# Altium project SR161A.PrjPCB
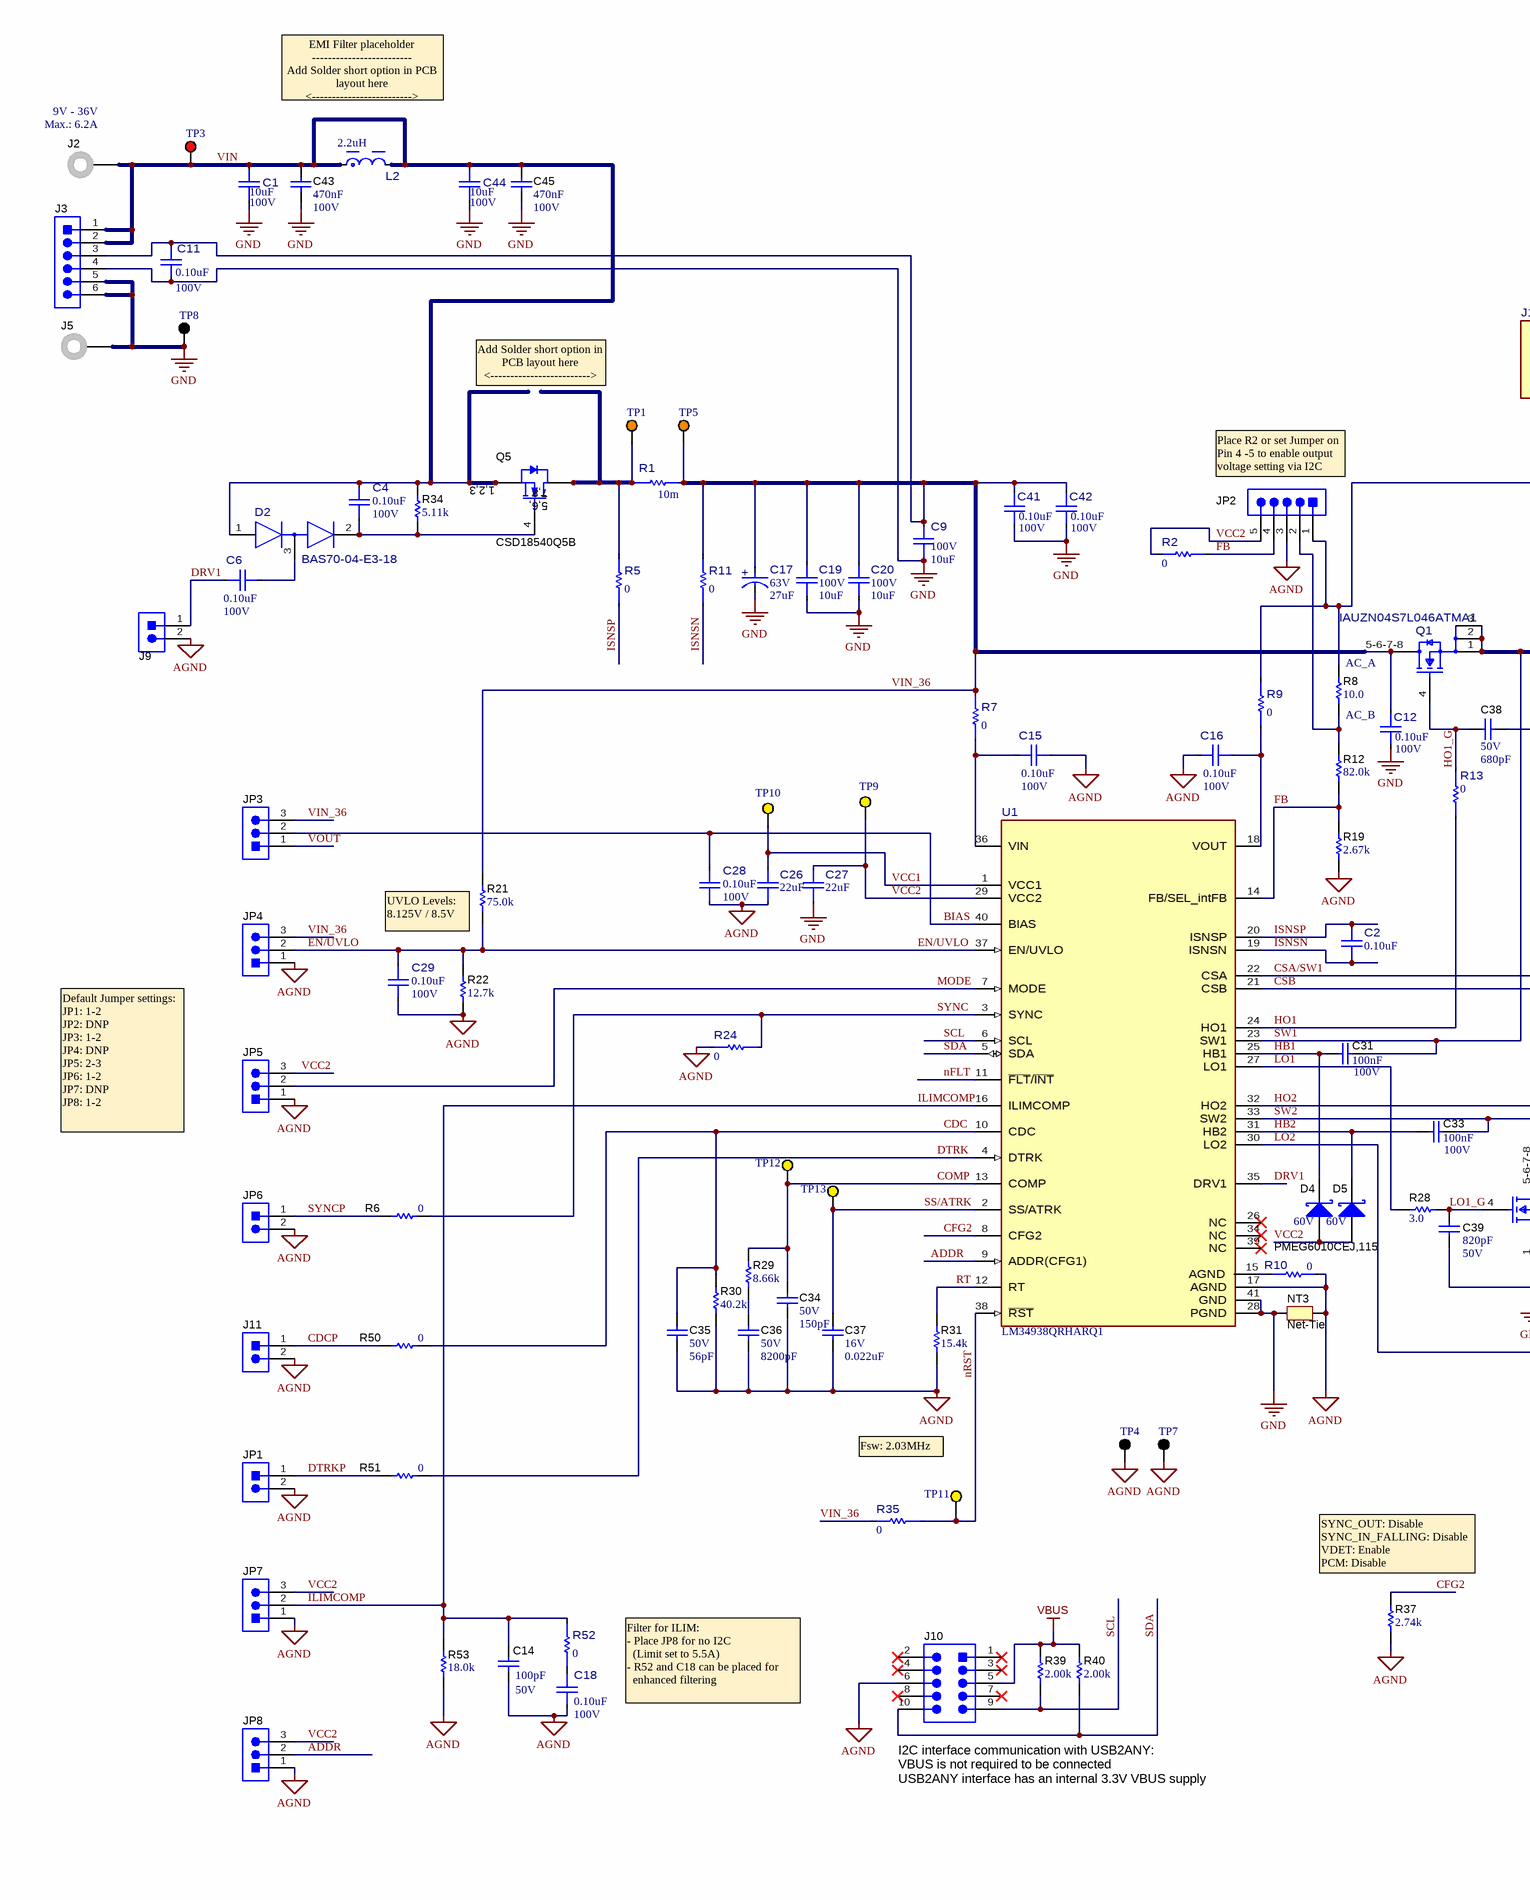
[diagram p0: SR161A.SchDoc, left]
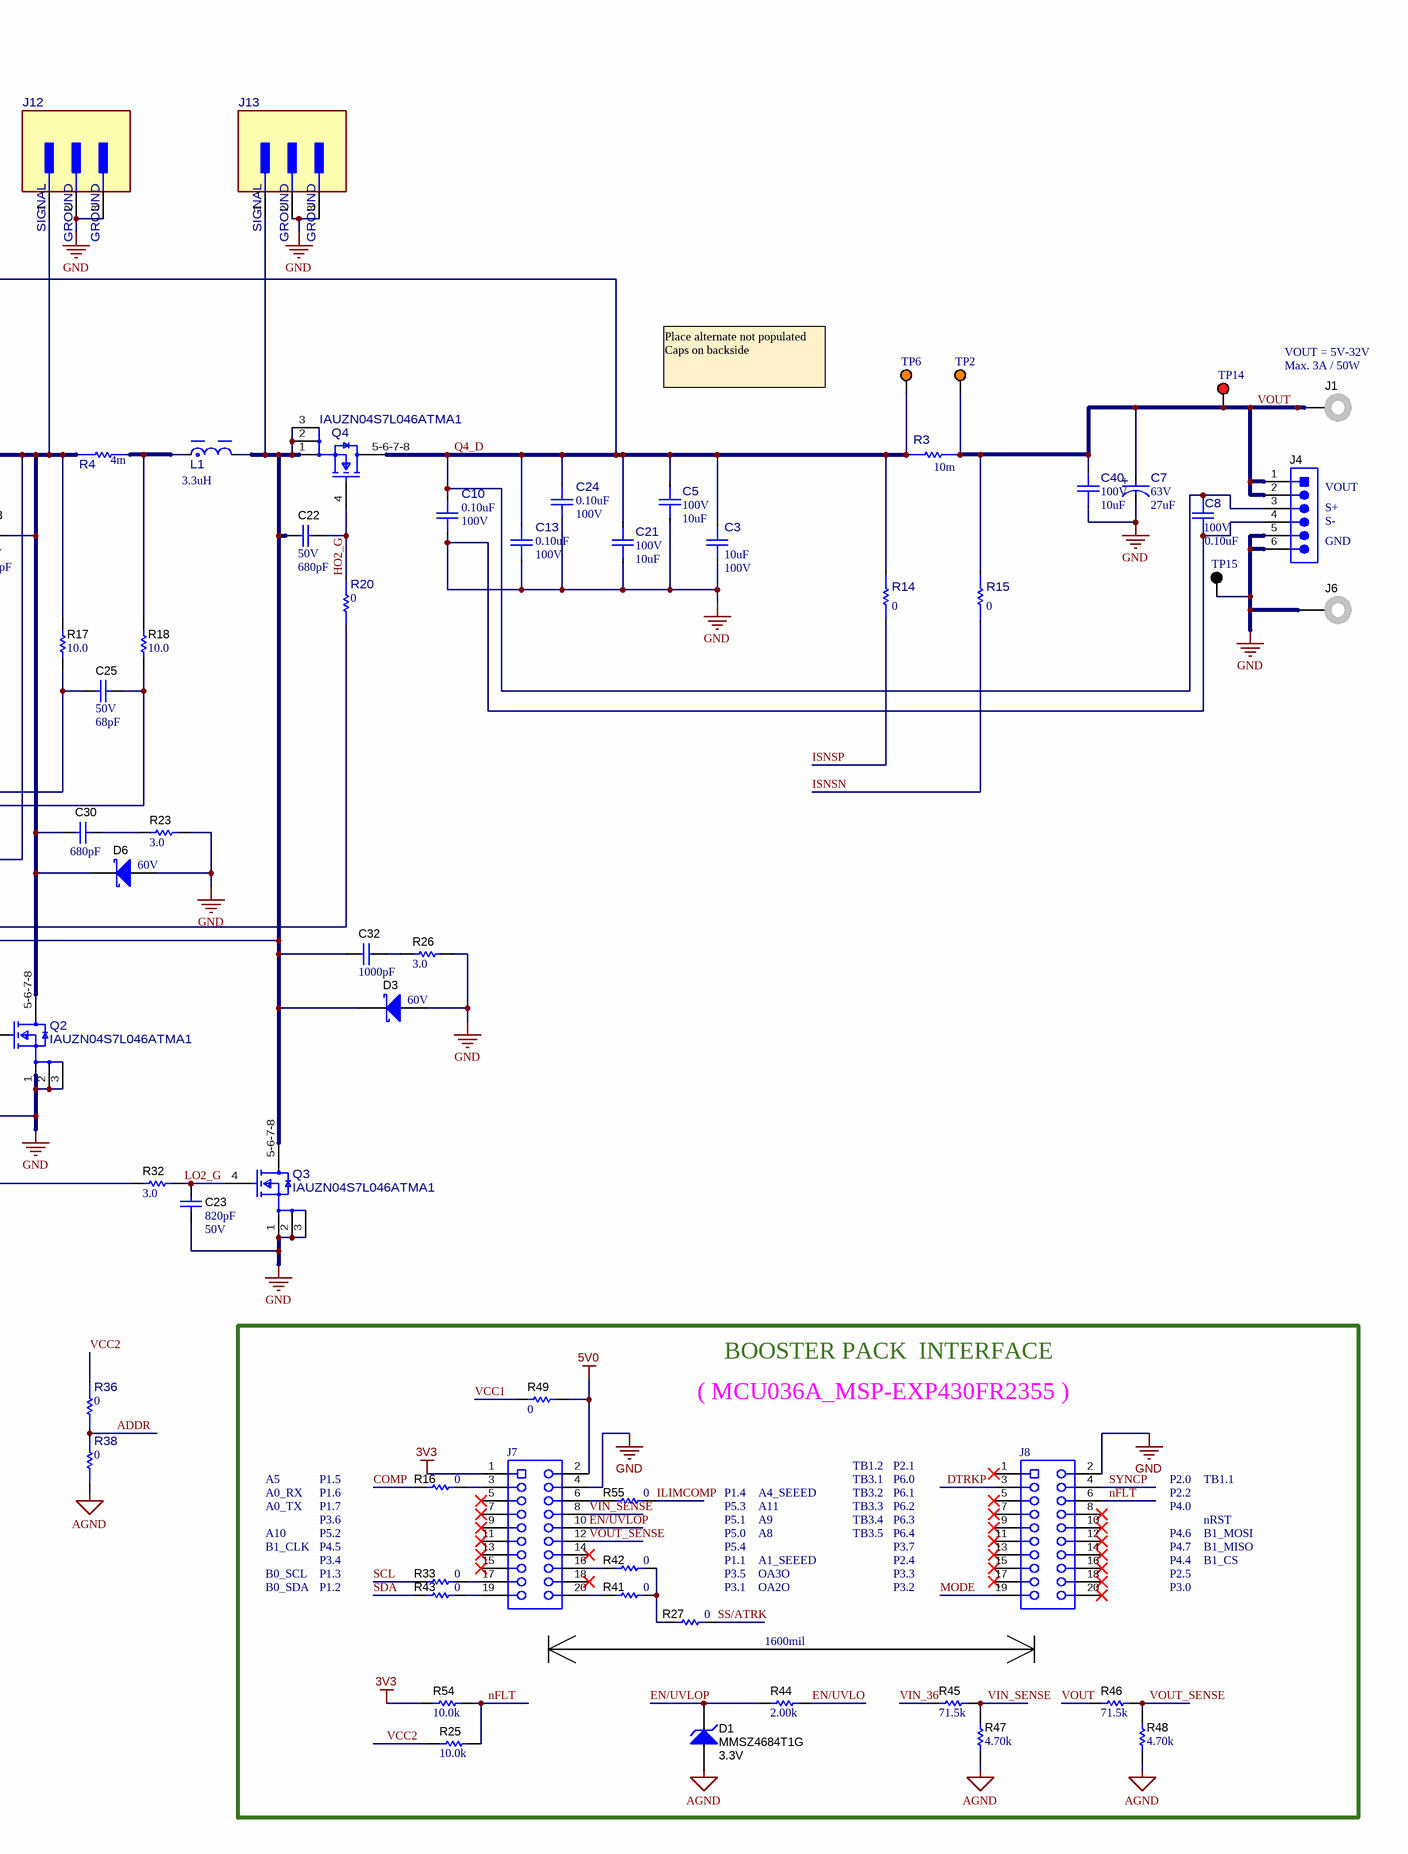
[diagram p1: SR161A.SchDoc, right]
CopyrightYear: 2025; PCB_Rev: A; PRJ_Customer: Public Release; PRJ_Number: SR161; PRJ_Title: LM34938Q1EVM-HD; SCH_Rev: A; TechSupport: http://www.ti.com/support; TID: N/A
2 sheets, 188 parts. Net scope: global (net labels, ports and power ports of the same name join across sheets).
Board file: SR161A.PcbDoc
Sheets:
  SR161A.SchDoc
  SR161A_Hardware.SchDoc

## Sheet SR161A.SchDoc: LM51772RWE EVM Schematic
size 558 x 431 mm; Date: Not shown in title block; ApprovedBy: Not shown in title block; CheckedBy: Not shown in title block; Author: Not shown in title block; CompanyName: Not shown in title block; Engineer: Not shown in title block; Organization: Not shown in title block; Address1: Not shown in title block; Address2: Not shown in title block; Address3: Not shown in title block; Address4: Not shown in title block; DocumentNumber: 1; Revision: Use project parameter SCH_Rev; SheetNumber: 1; SheetTotal: 2; PageSetup: Record=PageOptions¦CenterHorizontal=True¦CenterVertical=True¦PrintScale=1.00¦XCorrection=1.00¦YCorrection=1.00¦PrintKind=0¦BorderSize=5000000¦LeftOffset=0¦BottomOffset=0¦Orientation=2¦PaperLength=1000¦PaperWidth=1000¦Scale=100¦PaperSource=15¦PrintQuality=600¦MediaType=1¦DitherType=10¦PaperKind=Letter¦PrintScaleMode=1

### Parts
C1  VDC_V: 100V  ValueDisplayed: 10uF  [FP-C3225X7R2A106K250AC_1210-MFG]  (hidden comment: C3225X7R2A106K250AC)
C2  ValueDisplayed: 0.10uF  [FP-GRM155R62A104ME14D_0402-S]  (hidden comment: GRM155R62A104ME14D)
C3  VDC_V: 100V  ValueDisplayed: 10uF  [FP-C3225X7R2A106K250AC_1210-MFG]  (hidden comment: C3225X7R2A106K250AC)
C4  VDC_V: 100V  ValueDisplayed: 0.10uF  [FP-GRM155R62A104ME14D_0402-S]  (hidden comment: GRM155R62A104ME14D)
C5  VDC_V: 100V  ValueDisplayed: 10uF  [FP-C3225X7R2A106K250AC_1210-MFG]  (hidden comment: C3225X7R2A106K250AC)
C6  VDC_V: 100V  ValueDisplayed: 0.10uF  [FP-GRM155R62A104ME14D_0402-S]  (hidden comment: GRM155R62A104ME14D)
C7  VDC_V: 63V  ValueDisplayed: 27uF  [FP-A768KE276M1JLAE054_SMT_CAP_8MM3_8MM3-0]  (hidden comment: A768KE276M1JLAE054)
C8  VDC_V: 100V  ValueDisplayed: 0.10uF  [FP-GRM155R62A104ME14D_0402-S]  (hidden comment: GRM155R62A104ME14D)
C9  VDC_V: 100V  ValueDisplayed: 10uF  [FP-C3225X7R2A106K250AC_1210-MFG]  (hidden comment: C3225X7R2A106K250AC)
C10  VDC_V: 100V  ValueDisplayed: 0.10uF  [FP-GRM155R62A104ME14D_0402-S]  (hidden comment: GRM155R62A104ME14D)
C11  VDC_V: 100V  ValueDisplayed: 0.10uF  [FP-GRM155R62A104ME14D_0402-S]  (hidden comment: GRM155R62A104ME14D)
C12  VDC_V: 100V  ValueDisplayed: 0.10uF  [FP-GRM155R62A104ME14D_0402-S]  (hidden comment: GRM155R62A104ME14D)
C13  VDC_V: 100V  ValueDisplayed: 0.10uF  [FP-GRM155R62A104ME14D_0402-S]  (hidden comment: GRM155R62A104ME14D)
C14  VDC_V: 50V  ValueDisplayed: 100pF  [0402S]  (hidden comment: 04025A101FAT2A)
C15  VDC_V: 100V  ValueDisplayed: 0.10uF  [FP-GRM155R62A104ME14D_0402-S]  (hidden comment: GRM155R62A104ME14D)
C16  VDC_V: 100V  ValueDisplayed: 0.10uF  [FP-GRM155R62A104ME14D_0402-S]  (hidden comment: GRM155R62A104ME14D)
C17  VDC_V: 63V  ValueDisplayed: 27uF  [FP-A768KE276M1JLAE054_SMT_CAP_8MM3_8MM3-0]  (hidden comment: A768KE276M1JLAE054)
C18  VDC_V: 100V  ValueDisplayed: 0.10uF  [FP-GRM155R62A104ME14D_0402-S]  (hidden comment: GRM155R62A104ME14D)
C19  VDC_V: 100V  ValueDisplayed: 10uF  [FP-C3225X7R2A106K250AC_1210-MFG]  (hidden comment: C3225X7R2A106K250AC)
C20  VDC_V: 100V  ValueDisplayed: 10uF  [FP-C3225X7R2A106K250AC_1210-MFG]  (hidden comment: C3225X7R2A106K250AC)
C21  VDC_V: 100V  ValueDisplayed: 10uF  [FP-C3225X7R2A106K250AC_1210-MFG]  (hidden comment: C3225X7R2A106K250AC)
C22  VDC_V: 50V  ValueDisplayed: 680pF  [0402S]  (hidden comment: GRM1555C1H681JA01D)
C23  VDC_V: 50V  ValueDisplayed: 820pF  [0402S]  (hidden comment: GRM1555C1H821JA01D)
C24  VDC_V: 100V  ValueDisplayed: 0.10uF  [FP-GRM155R62A104ME14D_0402-S]  (hidden comment: GRM155R62A104ME14D)
C25  VDC_V: 50V  ValueDisplayed: 68pF  [0402S]  (hidden comment: GRM1555C1H680JA01D)
C26  ValueDisplayed: 22uF  [0603S]  (hidden comment: GRT188R61A226ME13D)
C27  ValueDisplayed: 22uF  [0603S]  (hidden comment: GRT188R61A226ME13D)
C28  VDC_V: 100V  ValueDisplayed: 0.10uF  [FP-GRM155R62A104ME14D_0402-S]  (hidden comment: GRM155R62A104ME14D)
C29  VDC_V: 100V  ValueDisplayed: 0.10uF  [FP-GRM155R62A104ME14D_0402-S]  (hidden comment: GRM155R62A104ME14D)
C30  ValueDisplayed: 680pF  [0805_HV]  (hidden comment: GRM2195C2A681JA01D)
C31  Cap_F: 100nF  VDC_V: 100V  [0603S]  (hidden comment: GRM188R72A104KA35D)
C32  ValueDisplayed: 1000pF  [0805_HV]  (hidden comment: GRM2195C2A102JA01D)
C33  Cap_F: 100nF  VDC_V: 100V  [0603S]  (hidden comment: GRM188R72A104KA35D)
C34  VDC_V: 50V  ValueDisplayed: 150pF  [0402S]  (hidden comment: GRM1555C1H151JA01D)
C35  VDC_V: 50V  ValueDisplayed: 56pF  [0402S]  (hidden comment: GRM1555C1H560JA01D)
C36  VDC_V: 50V  ValueDisplayed: 8200pF  [0402S]  (hidden comment: GRM155R71H822KA88D)
C37  VDC_V: 16V  ValueDisplayed: 0.022uF  [0402S]  (hidden comment: GRM155R71C223KA01D)
C38  VDC_V: 50V  ValueDisplayed: 680pF  [0402S]  (hidden comment: GRM1555C1H681JA01D)
C39  VDC_V: 50V  ValueDisplayed: 820pF  [0402S]  (hidden comment: GRM1555C1H821JA01D)
C40  VDC_V: 100V  ValueDisplayed: 10uF  [FP-C3225X7R2A106K250AC_1210-MFG]  (hidden comment: C3225X7R2A106K250AC)
C41  VDC_V: 100V  ValueDisplayed: 0.10uF  [FP-GRM155R62A104ME14D_0402-S]  (hidden comment: GRM155R62A104ME14D)
C42  VDC_V: 100V  ValueDisplayed: 0.10uF  [FP-GRM155R62A104ME14D_0402-S]  (hidden comment: GRM155R62A104ME14D)
C43  Cap_F: 470nF  VDC_V: 100V  [0805L]  (hidden comment: GRM21BR72A474KA73L)
C44  VDC_V: 100V  ValueDisplayed: 10uF  [FP-C3225X7R2A106K250AC_1210-MFG]  (hidden comment: C3225X7R2A106K250AC)
C45  Cap_F: 470nF  VDC_V: 100V  [0805L]  (hidden comment: GRM21BR72A474KA73L)
D1  MMSZ4684T1G  value 3.3V  [SOD-123]
D2  BAS70-04-E3-18  [FP-BAS70-04-E3-18_SOT23-3-MFG]
D3  value 60V  [SOD-123]  (hidden comment: PMEG6010CEGWJ)
D4  value 60V  [SOD-323F]  (hidden comment: PMEG6010CEJ,115)
D5  PMEG6010CEJ,115  value 60V  [SOD-323F]
D6  value 60V  [SOD-123]  (hidden comment: PMEG6010CEGWJ)
J1  108-0740-001  [Johnson_108-0740-001]  (value not drawn)
J2  108-0740-001  [Johnson_108-0740-001]  (value not drawn)
J3  61300611121  [WURTH_61300611121]  (value not drawn)
J4  61300611121  [WURTH_61300611121]  (value not drawn)
J5  108-0740-001  [Johnson_108-0740-001]  (value not drawn)
J6  108-0740-001  [Johnson_108-0740-001]  (value not drawn)
J7  SSQ-110-03-T-D  [Samtec_SSQ-110-03-x-D]  (value not drawn)
J8  SSQ-110-03-T-D  [Samtec_SSQ-110-03-x-D]  (value not drawn)
J9  61300211121  [WURTH_61300211121]  (value not drawn)
J10  N2510-6002-RB  [CONN_2510-6002]  (value not drawn)
J11  61300211121  [WURTH_61300211121]  (value not drawn)
J12  RSP-122811-01  [FP-RSP-122811-01_CONN_UFL-MFG]  (value not drawn)
J13  RSP-122811-01  [FP-RSP-122811-01_CONN_UFL-MFG]  (value not drawn)
JP1  61300211121  [WURTH_61300211121]  (value not drawn)
JP2  61300511121  [Wurth_61300511121]  (value not drawn)
JP3  61300311121  [WURTH_61300311121]  (value not drawn)
JP4  61300311121  [WURTH_61300311121]  (value not drawn)
JP5  61300311121  [WURTH_61300311121]  (value not drawn)
JP6  61300211121  [WURTH_61300211121]  (value not drawn)
JP7  61300311121  [WURTH_61300311121]  (value not drawn)
JP8  61300311121  [WURTH_61300311121]  (value not drawn)
L1  value 3.3uH  [FP-744393465033_SMT_IND_6MM4_6MM6-MFG]  (hidden comment: 744393465033)
L2  value 2.2uH  [FP-7443845030022_SMT_IND_5MM4_5MM4-MFG]  (hidden comment: 7443845030022)
NT3  Net-Tie  [Net-Tie_10mil]  (net tie, no BOM)
Q1  IAUZN04S7L046ATMA1  [FP-NVTFS5C673NLTAG_WDFN8-Recommended_Land_Pattern]
Q2  IAUZN04S7L046ATMA1  [FP-NVTFS5C673NLTAG_WDFN8-Recommended_Land_Pattern]
Q3  IAUZN04S7L046ATMA1  [FP-NVTFS5C673NLTAG_WDFN8-Recommended_Land_Pattern]
Q4  IAUZN04S7L046ATMA1  [FP-NVTFS5C673NLTAG_WDFN8-Recommended_Land_Pattern]
Q5  CSD18540Q5B  [DNK0008A]
R1  value 10m  [FP-KRL2012E-C-R010-F-T05_0508-MFG]  (hidden comment: KRL2012E-C-R010-F-T05)
R2  value 0  [FP-ERJ-2GE0R00X_0402-MFG]  (hidden comment: ERJ-2GE0R00X)
R3  value 10m  [FP-KRL2012E-C-R010-F-T05_0508-MFG]  (hidden comment: KRL2012E-C-R010-F-T05)
R4  value 4m  [FP-KRL2012E-M-R004-F-T5_2012-MFG]  (hidden comment: KRL2012E-M-R004-F-T5)
R5  value 0  [FP-ERJ-2GE0R00X_0402-MFG]  (hidden comment: ERJ-2GE0R00X)
R6  ValueDisplayed: 0  [0603S]  (hidden comment: RMCF0603ZT0R00)
R7  value 0  [FP-ERJ-2GE0R00X_0402-MFG]  (hidden comment: ERJ-2GE0R00X)
R8  ValueDisplayed: 10.0  [0402S]  (hidden comment: CRCW040210R0FKED)
R9  value 0  [FP-ERJ-2GE0R00X_0402-MFG]  (hidden comment: ERJ-2GE0R00X)
R10  value 0  [FP-ERJ-2GE0R00X_0402-MFG]  (hidden comment: ERJ-2GE0R00X)
R11  value 0  [FP-ERJ-2GE0R00X_0402-MFG]  (hidden comment: ERJ-2GE0R00X)
R12  ValueDisplayed: 82.0k  [0402S]  (hidden comment: RC0402FR-0782KL)
R13  value 0  [FP-ERJ-2GE0R00X_0402-MFG]  (hidden comment: ERJ-2GE0R00X)
R14  value 0  [FP-ERJ-2GE0R00X_0402-MFG]  (hidden comment: ERJ-2GE0R00X)
R15  value 0  [FP-ERJ-2GE0R00X_0402-MFG]  (hidden comment: ERJ-2GE0R00X)
R16  ValueDisplayed: 0  [0603S]  (hidden comment: RMCF0603ZT0R00)
R17  ValueDisplayed: 10.0  [0402S]  (hidden comment: CRCW040210R0FKED)
R18  ValueDisplayed: 10.0  [0402S]  (hidden comment: CRCW040210R0FKED)
R19  ValueDisplayed: 2.67k  [0402S]  (hidden comment: CRCW04022K67FKED)
R20  value 0  [FP-ERJ-2GE0R00X_0402-MFG]  (hidden comment: ERJ-2GE0R00X)
R21  ValueDisplayed: 75.0k  [0402S]  (hidden comment: CRCW040275K0FKED)
R22  ValueDisplayed: 12.7k  [0402S]  (hidden comment: CRCW040212K7FKED)
R23  ValueDisplayed: 3.0  [1206]  (hidden comment: CRCW12063R00JNEA)
R24  value 0  [FP-ERJ-2GE0R00X_0402-MFG]  (hidden comment: ERJ-2GE0R00X)
R25  ValueDisplayed: 10.0k  [0402S]  (hidden comment: MCS0402MD1002BE100)
R26  ValueDisplayed: 3.0  [1206]  (hidden comment: CRCW12063R00JNEA)
R27  ValueDisplayed: 0  [0603S]  (hidden comment: RMCF0603ZT0R00)
R28  ValueDisplayed: 3.0  [0402S]  (hidden comment: CRCW04023R00JNED)
R29  ValueDisplayed: 8.66k  [0402S]  (hidden comment: CRCW04028K66FKED)
R30  ValueDisplayed: 40.2k  [0402S]  (hidden comment: CRCW040240K2FKED)
R31  ValueDisplayed: 15.4k  [0402S]  (hidden comment: CRCW040215K4FKED)
R32  ValueDisplayed: 3.0  [0402S]  (hidden comment: CRCW04023R00JNED)
R33  ValueDisplayed: 0  [0603S]  (hidden comment: RMCF0603ZT0R00)
R34  ValueDisplayed: 5.11k  [0402S]  (hidden comment: CRCW04025K11FKED)
R35  value 0  [FP-ERJ-2GE0R00X_0402-MFG]  (hidden comment: ERJ-2GE0R00X)
R36  value 0  [FP-ERJ-2GE0R00X_0402-MFG]  (hidden comment: ERJ-2GE0R00X)
R37  ValueDisplayed: 2.74k  [0402S]  (hidden comment: CRCW04022K74FKED)
R38  value 0  [FP-ERJ-2GE0R00X_0402-MFG]  (hidden comment: ERJ-2GE0R00X)
R39  ValueDisplayed: 2.00k  [0603S]  (hidden comment: RC0603FR-072KL)
R40  ValueDisplayed: 2.00k  [0603S]  (hidden comment: RC0603FR-072KL)
R41  ValueDisplayed: 0  [0603S]  (hidden comment: RMCF0603ZT0R00)
R42  ValueDisplayed: 0  [0603S]  (hidden comment: RMCF0603ZT0R00)
R43  ValueDisplayed: 0  [0603S]  (hidden comment: RMCF0603ZT0R00)
R44  ValueDisplayed: 2.00k  [0603S]  (hidden comment: RC0603FR-072KL)
R45  ValueDisplayed: 71.5k  [0603S]  (hidden comment: RC0603FR-0771K5L)
R46  ValueDisplayed: 71.5k  [0603S]  (hidden comment: RC0603FR-0771K5L)
R47  ValueDisplayed: 4.70k  [0603S]  (hidden comment: RC0603FR-074K7L)
R48  ValueDisplayed: 4.70k  [0603S]  (hidden comment: RC0603FR-074K7L)
R49  ValueDisplayed: 0  [0603S]  (hidden comment: RMCF0603ZT0R00)
R50  ValueDisplayed: 0  [0603S]  (hidden comment: RMCF0603ZT0R00)
R51  ValueDisplayed: 0  [0603S]  (hidden comment: RMCF0603ZT0R00)
R52  value 0  [FP-ERJ-2GE0R00X_0402-IPC_C]  (hidden comment: ERJ-2GE0R00X)
R53  ValueDisplayed: 18.0k  [0603S]  (hidden comment: RC0603FR-0718KL)
R54  ValueDisplayed: 10.0k  [0603S]  (hidden comment: RT0603BRD0710KL)
R55  ValueDisplayed: 0  [0603S]  (hidden comment: RMCF0603ZT0R00)
TP1  5003  [Keystone5003]  (value not drawn)
TP2  5003  [Keystone5003]  (value not drawn)
TP3  5000  [Keystone5000]  (value not drawn)
TP4  5001  [Keystone5001]  (value not drawn)
TP5  5003  [Keystone5003]  (value not drawn)
TP6  5003  [Keystone5003]  (value not drawn)
TP7  5001  [Keystone5001]  (value not drawn)
TP8  5001  [Keystone5001]  (value not drawn)
TP9  5004  [Keystone5004]  (value not drawn)
TP10  5004  [Keystone5004]  (value not drawn)
TP11  5004  [Keystone5004]  (value not drawn)
TP12  5004  [Keystone5004]  (value not drawn)
TP13  5004  [Keystone5004]  (value not drawn)
TP14  5000  [Keystone5000]  (value not drawn)
TP15  5001  [Keystone5001]  (value not drawn)
U1  LM34938QRHARQ1  [RHA0040P-MFG]

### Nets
3V3: J7.1 R54.2
5V0: J7.2 R49.2
AGND: C14.2 C15.1 C16.2 C18.2 C26.1 C28.1 C29.2 C34.2 C35.2 C36.2 C37.2 D1.2(A) J9.2 J10.6 J11.2 JP1.2 JP2.3 JP4.1 JP5.1 JP6.2 JP7.1 JP8.1 NT3.2 R10.1 R19.1 R22.1 R24.2 R30.1 R31.1 R37.1 R38.2 R47.1 R48.1 R53.1 TP4.1 TP7.1 U1.17(AGND)
GND: C1.1 C3.1 C5.1 C7.1(CATHODE) C8.1 C9.1 C10.1 C11.2 C12.2 C13.1 C17.1(CATHODE) C19.1 C20.1 C21.1 C23.2 C24.1 C27.1 C39.2 C40.1 C41.2 C42.2 C43.2 C44.1 C45.2 D3.2(A) D6.2(A) J3.4 J3.5 J3.6 J4.4 J4.5 J4.6 J5.1 J6.1 J7.4 J8.2 J12.2(GROUND) J12.3(GROUND) J13.2(GROUND) J13.3(GROUND) NT3.1 Q2.1(S) Q2.2(S) Q2.3(S) Q3.1(S) Q3.2(S) Q3.3(S) R23.2 R26.2 TP8.1 TP15.1 U1.28(PGND) U1.41(GND)
VBUS: J10.5 R39.2 R40.2
ADDR: JP8.2 R36.2 R38.1 U1.9(ADDR(CFG1))
BIAS: C28.2 JP3.2 U1.40(BIAS)
CDC: C35.1 R30.2 R50.1 U1.10(CDC)
CDCP: J11.1 R50.2
CFG2: R37.2 U1.8(CFG2)
COMP: C34.1 R16.2 R29.2 TP12.1 U1.13(COMP)
CSA/SW1: C25.2 R17.1 U1.22(CSA)
CSB: C25.1 R18.1 U1.21(CSB)
DRV1: C6.1 J9.1 U1.35(DRV1)
DTRK: R51.1 U1.4(DTRK)
DTRKP: J8.3 JP1.1 R51.2
EN/UVLO: C29.1 JP4.2 R21.1 R22.2 R44.1 U1.37(EN/UVLO)
EN/UVLOP: D1.1(K) J7.10 R44.2
FB: JP2.4 R2.1 R12.1 R19.2 U1.14(FB/SEL_intFB)
HB1: C31.2 D4.1(K) U1.25(HB1)
HB2: C33.2 D5.1(K) U1.31(HB2)
HO1: R13.2 U1.24(HO1)
HO1_G: C38.1 Q1.4(G) R13.1
HO2: R20.2 U1.32(HO2)
HO2_G: C22.2 Q4.4(G) R20.1
ILIMCOMP: C14.1 JP7.2 R52.2 R53.2 R55.1 U1.16(ILIMCOMP)
ISNSN: C2.1 R11.1 R15.1 U1.19(ISNSN)
ISNSP: C2.2 R5.1 R14.1 U1.20(ISNSP)
LO1: R28.1 U1.27(LO1)
LO1_G: C39.1 Q2.4(G) R28.2
LO2: R32.1 U1.30(LO2)
LO2_G: C23.1 Q3.4(G) R32.2
MODE: J8.19 JP5.2 U1.7(MODE)
nFLT: J8.6 R25.1 R54.1 U1.11(~{FLT}/~{INT})
nRST: R35.1 TP11.1 U1.38(~{RST})
Q4_D: C3.2 C5.2 C8.2 C10.2 C13.2 C21.2 C24.2 J4.3 JP2.1 Q4.5-6-7-8(D) R3.1 R8.2 R9.2 R14.2 TP6.1
RT: R31.2 U1.12(RT)
SCL: J10.9 R33.2 R39.1 U1.6(SCL)
SDA: J10.10 R40.1 R43.2 U1.5(SDA)
SS/ATRK: C37.1 R27.1 TP13.1 U1.2(SS/ATRK)
SW1: C30.2 C31.1 C38.2 D6.1(K) J12.1(SIGNAL) Q1.1(S) Q1.2(S) Q1.3(S) Q2.5-6-7-8(D) R4.1 R17.2 U1.23(SW1)
SW2: C22.1 C32.1 C33.1 D3.1(K) J13.1(SIGNAL) L1.2 Q3.5-6-7-8(D) Q4.1(S) Q4.2(S) Q4.3(S) U1.33(SW2)
SYNC: R6.1 R24.1 U1.3(SYNC)
SYNCP: J8.4 JP6.1 R6.2
VCC1: C26.2 R49.1 TP10.1 U1.1(VCC1)
VCC2: C27.2 D4.2(A) D5.2(A) JP2.5 JP5.3 JP7.3 JP8.3 R2.2 R25.2 R36.1 TP9.1 U1.29(VCC2)
VIN: C1.2 C4.2 C43.1 C44.2 C45.1 D2.1(1_ANODE) J2.1 J3.1 J3.2 L2.1 L2.2 Q5.1(S) Q5.2(S) Q5.3(S) R34.2 TP3.1
VIN_36: C9.2 C11.1 C12.1 C17.2(ANODE) C19.2 C20.2 C41.1 C42.1 J3.3 JP3.3 JP4.3 Q1.5-6-7-8(D) R1.2 R7.2 R11.2 R21.2 R35.2 R45.1 TP5.1
VIN_SENSE: J7.8 R45.2 R47.2
VOUT: C7.2(ANODE) C40.2 J1.1 J4.1 J4.2 JP3.1 R3.2 R15.2 R46.1 TP2.1 TP14.1
VOUT_SENSE: J7.12 R46.2 R48.2
NetC4_1: C4.1 D2.2(2_CATHODE) Q5.4(G) R34.1
NetC6_2: C6.2 D2.3(1_CATHODE/2_ANODE)
NetC15_2: C15.2 R7.1 U1.36(VIN)
NetC16_1: C16.1 R9.1 U1.18(VOUT)
NetC18_1: C18.1 R52.1
NetC30_1: C30.1 R23.1
NetC32_2: C32.2 R26.1
NetC36_1: C36.1 R29.1
NetJ7_3: J7.3 R16.1
NetJ7_6: J7.6 R55.2
NetJ7_16: J7.16 R42.2
NetJ7_17: J7.17 R33.1
NetJ7_19: J7.19 R43.1
NetJ7_20: J7.20 R41.2
NetJP2_2: JP2.2 R8.1 R12.2
NetL1_1: L1.1 R4.2 R18.2
NetQ5_5: Q5.5(D) Q5.6(D) Q5.7(D) Q5.8(D) Q5.9(D) R1.1 R5.2 TP1.1
NetR10_2: R10.2 U1.15(AGND)
NetR27_2: R27.2 R41.1 R42.1

Not connected (* = marked no-connect by the designer): J7 5* 7* 9* 11* 13* 14* 15* 18*; J8 1* 5* 7* 8* 9* 10* 11* 12* 13* 14* 15* 16* 17* 18* 20*; J10 1* 2* 3* 4* 7* 8*; U1 26(NC)* 34(NC)* 39(NC)*

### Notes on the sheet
- EMI Filter placeholder
  -------------------------
  Add Solder short option in PCB layout here
  <------------------------->
- (near J2) 9V - 36V
- (near J2) Max.: 6.2A
- Add Solder short option in PCB layout here
  <------------------------->
- (near JP2) Place R2 or set Jumper on Pin 4 -5 to enable output voltage setting via I2C
- VOUT = 5V-32V
- Place alternate not populated Caps on backside
- (near J1) Max. 3A / 50W
- (near R8) AC_A
- (near J4) VOUT
- (near R8) AC_B
- (near J4) S+
- (near J4) S-
- (near J4) GND
- (near R21) UVLO Levels:
  8.125V / 8.5V
- Default Jumper settings:
  JP1: 1-2
  JP2: DNP
  JP3: 1-2
  JP4: DNP
  JP5: 2-3
  JP6: 1-2
  JP7: DNP
  JP8: 1-2
- Fsw: 2.03MHz
- BOOSTER PACK  INTERFACE
- (near R37) SYNC_OUT: Disable
  SYNC_IN_FALLING: Disable
  VDET: Enable
  PCM: Disable
- ( MCU036A_MSP-EXP430FR2355 )
- A5
- A0_RX
- P1.5
- P1.6
- P1.4
- A4_SEEED
- TB1.2
- TB3.1
- TB3.2
- P2.1
- P6.0
- P6.1
- P2.0
- P2.2
- TB1.1
- Filter for ILIM:
  - Place JP8 for no I2C
  (Limit set to 5.5A)
  - R52 and C18 can be placed for
  enhanced filtering
- A0_TX
- A10
- B1_CLK
- B0_SCL
- P1.7
- P3.6
- P5.2
- P4.5
- P3.4
- P1.3
- P5.3
- P5.1
- P5.0
- P5.4
- P1.1
- (near R27) P3.5
- A11
- A9
- A8
- A1_SEEED
- OA3O
- TB3.3
- TB3.4
- TB3.5
- P6.2
- P6.3
- P6.4
- P3.7
- P2.4
- P3.3
- P4.0
- P4.6
- P4.7
- P4.4
- P2.5
- nRST
- B1_MOSI
- B1_MISO
- B1_CS
- B0_SDA
- P1.2
- (near R27) P3.1
- OA2O
- P3.2
- P3.0
- (near J10) I2C interface communication with USB2ANY:
  VBUS is not required to be connected
  USB2ANY interface has an internal 3.3V VBUS supply
- 1600mil

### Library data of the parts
C1 C3 C5 C9 C19-C21 C40 C44 = CMP-0096021-1: 10 µF ±10% 100V Ceramic Capacitor X7R 1210 (3225 Metric); Manufacturer: TDK; Cap_F: 10µF; AEC Qualified: No; Value: 10µF; SizeZ_mm: 2.85mm; TempCo: 15%
C2 C4 C6 C8 C10-C13 C15 C16 C18 C24 C28 C29 C41 C42 = CMP-0093748-2: Chip Multilayer Ceramic Capacitors for General Purpose, 0402, 0.10uF, X5R, 15%, 20%, 100V; Manufacturer: Murata; AEC Qualified: No; Cap_F: 100nF; SizeZ_mm: 0.55mm; Value: 100nF
C7 C17 = CMP-0097690-1: Cap Aluminum Polymer 27uF 63V 20% Solder Cylindrical 54m Ohm 1175mA 2000 hr 125°C T/R; Manufacturer: KEMET; Life: 2000Hours; Cap_F: 27µF; Value: 27µF; Leakage Current: 340uA; SizeZ_mm: 7mm; IRMS_A: 1.175A; AEC Qualified: No
C14 = CMP-0006196-2: CAP, CERM, 100 pF, 50 V, +/- 1%, C0G/NP0, 0402; Manufacturer: AVX; TaMin_C: -55°C; Polarized: N; SizeAreaWB_mm2: 3; Value1: Unknown; U/M: EA; Value: 100pF; TaMax_C: 125°C; SizeZ_mm: 0.6; SizeX_mm: 1; SizeY_mm: 0.5; Cap_Case: 0402; AEC Category: Q200
C22 C38 = CMP-0006486-2: CAP, CERM, 680 pF, 50 V, +/- 5%, C0G/NP0, 0402; Manufacturer: MuRata; TaMin_C: -55°C; Polarized: N; SizeAreaWB_mm2: 3; Value1: Unknown; U/M: EA; Value: 680pF; TaMax_C: 125°C; SizeZ_mm: 0.6; SizeX_mm: 1; SizeY_mm: 0.5; Cap_Case: 0402; AEC Category: Q200
C23 C39 = CMP-0006493-2: CAP, CERM, 820 pF, 50 V, +/- 5%, C0G/NP0, 0402; Manufacturer: MuRata; TaMin_C: -55°C; Polarized: N; SizeAreaWB_mm2: 3; Value1: Unknown; U/M: EA; Value: 820pF; TaMax_C: 125°C; SizeZ_mm: 0.6; SizeX_mm: 1; SizeY_mm: 0.5; Cap_Case: 0402; AEC Category: Q200
C25 = CMP-0006485-2: CAP, CERM, 68 pF, 50 V, +/- 5%, C0G/NP0, 0402; Manufacturer: MuRata; TaMin_C: -55°C; Polarized: N; SizeAreaWB_mm2: 3; Value1: Unknown; U/M: EA; Value: 68pF; TaMax_C: 125°C; SizeZ_mm: 0.6; SizeX_mm: 1; SizeY_mm: 0.5; Cap_Case: 0402; AEC Category: Q200
C26 C27 = CMP-0092433-2: Multi-Layer Ceramic Capacitor 22uF 10V X5R ±20% 0603 Paper T/R; Manufacturer: Murata; Cap_F: 22µF; Value: 22µF; SizeZ_mm: 1mm; AEC Qualified: Yes; AEC Grade: Grade 3; TempCo: 15%
C30 = CMP-0008176-2: CAP, CERM, 680 pF, 100 V, +/- 5%, C0G/NP0, 0805; Manufacturer: MuRata; TaMin_C: -55°C; Polarized: N; SizeAreaWB_mm2: 6.75; Value1: Unknown; U/M: EA; Value: 680pF; TaMax_C: 125°C; SizeZ_mm: 1.45; SizeX_mm: 2; SizeY_mm: 1.25; Cap_Case: 0805; Value2: 100V; SizeArea_mm2: 2.5; AEC Category: Q200
C31 C33 = CMP-0007469-4: CAP, CERM, 0.1 uF, 100 V, +/- 10%, X7R, 0603; Manufacturer: MuRata; TaMin_C: -55°C; Polarized: N; SizeAreaWB_mm2: 4.68; Value1: Unknown; U/M: EA; Value: 0.1uF; TaMax_C: 125°C; SizeZ_mm: 1; SizeX_mm: 1.6; SizeY_mm: 0.8; Cap_Case: 0603; SizeArea_mm2: 1.28; AEC Category: Q200
C32 = CMP-0008168-2: CAP, CERM, 1000 pF, 100 V, +/- 5%, C0G/NP0, 0805; Manufacturer: MuRata; TaMin_C: -55°C; Polarized: N; SizeAreaWB_mm2: 6.75; Value1: Unknown; U/M: EA; Value: 1000pF; TaMax_C: 125°C; SizeZ_mm: 1.45; SizeX_mm: 2; SizeY_mm: 1.25; Cap_Case: 0805; Value2: 100V; SizeArea_mm2: 2.5; Cap_F: 1nF; AEC Category: Q200
C34 = CMP-0006421-2: CAP, CERM, 150 pF, 50 V, +/- 5%, C0G/NP0, 0402; Manufacturer: MuRata; TaMin_C: -55°C; Polarized: N; SizeAreaWB_mm2: 3; Value1: Unknown; U/M: EA; Value: 150pF; TaMax_C: 125°C; SizeZ_mm: 0.6; SizeX_mm: 1; SizeY_mm: 0.5; Cap_Case: 0402; AEC Category: Q200
C35 = CMP-0006478-2: CAP, CERM, 56 pF, 50 V, +/- 5%, C0G/NP0, 0402; Manufacturer: MuRata; TaMin_C: -55°C; Polarized: N; SizeAreaWB_mm2: 3; Value1: Unknown; U/M: EA; Value: 56pF; TaMax_C: 125°C; SizeZ_mm: 0.6; SizeX_mm: 1; SizeY_mm: 0.5; Cap_Case: 0402; AEC Category: Q200
C36 = CMP-0006698-2: CAP, CERM, 8200 pF, 50 V, +/- 10%, X7R, 0402; Manufacturer: MuRata; TaMin_C: -55°C; Polarized: N; SizeAreaWB_mm2: 3; Value1: Unknown; U/M: EA; Value: 8200pF; TaMax_C: 125°C; SizeZ_mm: 0.6; SizeX_mm: 1; SizeY_mm: 0.5; Cap_Case: 0402; Cap_F: 8.2nF; AEC Category: Q200
C37 = CMP-0006647-2: CAP, CERM, 0.022 uF, 16 V, +/- 10%, X7R, 0402; Manufacturer: MuRata; TaMin_C: -55°C; Polarized: N; SizeAreaWB_mm2: 3; Value1: Unknown; U/M: EA; TaMax_C: 125°C; SizeZ_mm: 0.6; SizeX_mm: 1; SizeY_mm: 0.5; Cap_Case: 0402; Cap_F: 22nF; AEC Category: Q200
C43 C45 = CMP-0008374-2: CAP, CERM, 0.47 uF, 100 V, +/- 10%, X7R, 0805; Manufacturer: MuRata; TaMin_C: -55°C; Polarized: N; SizeAreaWB_mm2: 6.75; Value1: Unknown; U/M: EA; Value: 0.47uF; TaMax_C: 125°C; SizeZ_mm: 1.45; SizeX_mm: 2; SizeY_mm: 1.25; Cap_Case: 0805; SizeArea_mm2: 2.5; AEC Category: Q200
D1 = CMP-0005781-3: Diode, Zener, 3.3 V, 500 mW, SOD-123; Manufacturer: ON Semiconductor; SizeArea_mm2: 6.545; SizeX_mm: 3.85; SizeY_mm: 1.7; AEC Category: Q101; Power_W: 500mW; Value1: 0.5W; RJA_CperW: 340; SizeZ_mm: 1.35; SizeAreaWB_mm2: 13.095
D2 = CMP-0096356-1: Diode Array 1 Pair Series Connection Schottky 70 V 200mA (DC) Surface Mount TO-236-3, SC-59, SOT-23-3; Manufacturer: Vishay; ValueDisplayed: 1.5pF; Vf_V: 70V; TJmax_C: 125°C; AEC Qualified: No; Peak Reverse Current: 0.02uA; SizeZ_mm: 1.15mm; Max Surge Forward Current: 600mA
D3 D6 = CMP-0079239-2: Diode, Schottky, 60 V, 1 A, AEC-Q101, SOD-123; Manufacturer: Nexperia; SizeY_mm: 1.7; AEC Qualified: Y; SizeArea_mm2: 6.545; Vf_V: 660mV; Value1: 1A; AEC Category: Q101; TJmax_C: 150°C; SizeX_mm: 3.85; SizeZ_mm: 1.35; SizeAreaWB_mm2: 13.095; Value2: 0.66V
D4 D5 = CMP-0077011-2: Diode, Schottky, 60 V, 1 A, SOD-323F; Manufacturer: Nexperia; SizeX_mm: 2.5; TJmax_C: 150°C; SizeZ_mm: 0.8; Green_Lifecycle: Not Set; Value2: 0.66V; SizeAreaWB_mm2: 7.875; Green_REACh: Incomplete; Io_A: 1A; SizeY_mm: 1.25; SizeArea_mm2: 3.125; Vf_V: 660mV; AEC Category: Q101
J1 J2 J5 J6 = CMP-0055387-2: Standard Banana Jack, Uninsulated, 15A; Manufacturer: Cinch Connectivity; CNHeader: FALSE; Green_Lifecycle: Active; Green_REACh: Passed; CT: TRUE
J3 J4 = CMP-0054801-2: Header, 2.54 mm, 6x1, Gold, TH; Manufacturer: Wurth Elektronik; Cert_UL: Y; Gender: Male; Row_Count: 1; Shrouded: N; Pitch_mm: 2.54
J7 J8 = CMP-0079854-1: Receptacle, 2.54mm, 10x2, Tin, TH; Manufacturer: Samtec; Cert_VDE: N; Current_A: 6.3A; Green_Lifecycle: Active; Gender: Female; Cert_CSA: Y; Green_REACh: Incomplete; Voltage_V: 550V; CompType: Socket Strip; Row_Count: 2; RowSpacing_mm: 2.54
J9 J11 JP1 JP6 = CMP-0054794-2: Header, 2.54 mm, 2x1, Gold, TH; Manufacturer: Wurth Elektronik; Shrouded: N; Gender: Male; Green_REACh: Passed; Pitch_mm: 2.54; Green_Lifecycle: Active; Row_Count: 1; Cert_UL: Y
J10 = CMP-0055448-2: Header (shrouded), 100mil, 5x2, High-Temperature, Gold, TH; Manufacturer: 3M; Green_Lifecycle: Active; Green_REACh: Passed
J12 J13 = CMP-0124001-1: U.FL (UMCC), I-PEX MHFI Connector Receptacle, Male Pin 50 Ohms Surface Mount Solder; Manufacturer: Samtec; Shrouded: true; Voltage_V: 60V; AEC Qualified: No; Conn Orientation: Vertical; Dielectric Material: Liquid Crystal Polymer; Frequency_Fixed: 6GHz; Impedance: 50Ω; SizeZ_mm: 1.35mm
JP2 = CMP-0084909-1: Header, 2.54mm, 5x1, Gold, TH; Manufacturer: Wurth Elektronik; Pitch_mm: 2.54; Current_A: 3A; Shrouded: N; Gender: Male; Voltage_V: 250V; Row_Count: 1
JP3-JP5 JP7 JP8 = CMP-0054796-4: Header, 2.54 mm, 3x1, Gold, TH; Manufacturer: Wurth Elektronik; Green_Lifecycle: Active; Green_REACh: Passed; CT: FALSE; CNHeader: TRUE
L1 = CMP-0127655-4: 3.3 µH Shielded Molded Inductor 20.4 A 6.5mOhm Max Nonstandard; Manufacturer: Wurth Electronics; AEC Grade: Grade 0; AEC Qualified: Yes; DCR_ohm: 6.5m; Ind_H: 3.3µH; Irms: 20.4A; Isat: 8.9A; Material: Iron; SizeZ_mm: 6.1mm; Self Resonant Frequency: 21MHz; Shrouded: true; TaMax_C: +110°C; TaMin_C: -55°C; Test Frequency: 100kHz; Tolerance_%: 20%
L2 = CMP-0126346-1: 2.2 µH Shielded Molded Inductor 12.4 A 9.3mOhm Max Nonstandard; Manufacturer: Wurth Electronics; AEC Qualified: No; DCR_ohm: 9.3m; Ind_H: 2.2µH; Irms: 12.4A; Isat: 5.2A; Material: Iron; SizeZ_mm: 3.1mm; Self Resonant Frequency: 35MHz; Shrouded: true; TaMax_C: +85°C; TaMin_C: -40°C; Test Frequency: 100kHz; Tolerance_%: 20%
NT3 = CMP-0078142-6: Single point connection between nets.
Q1-Q4 = CMP-0127418-3: MOSFET N-Channel 40 V 72A (Tj) 45W (Tc) Surface Mount PG-TSDSON-8-44; Manufacturer: Infineon; AEC Qualified: Yes; IdsMax_A: 60A; QgTyp_nC: 12nC @ 10V; Rdson45_ohm: 4.16m; SizeZ_mm: 1.1mm; VdsMax_V: 950mV; Vgs_V: 16V; AEC Grade: Grade 0; Drain To Source Breakdown Voltage: 40V; Input Capacitance At Vds: 810pF @ 20V; Number Of Channels: 1; Pulse Drain Current: 165A; Reverse Recovery Charge: 2.9nC; Reverse Recovery Time: 14ns; Rthja Max: 41K/W; Standoff Height: 0mm; Threshold Vgs Max: 1.8V; Threshold Vgs Min: 1.2V; TJmax_C: +175°C; Turn Off Delay Time: 9ns; Turn On Delay Time: 2ns; Typ Forward Diode Voltage: 0.8V; ChMode: Enhancement
Q5 = CMP-0000823-2: MOSFET, N-CH, 60 V, 100 A, DNK0008A (VSON-CLIP-8); Alternate Manufacturer: None; Manufacturer: Texas Instruments; SizeZ_mm: 1; ChType: N; Value2: 41 nC; Value1: 0.003; VdsMax_V: 60V; SizeX_mm: 6; SizeY_mm: 5; Vgs_V: 20V; Value: 60V; Rdson45_ohm: 3.3m; SizeArea_mm2: 30; AEC Category: Q101; IdsMax_A: 100A; SizeAreaWB_mm2: 56; U/M: EA; QgTyp_nC: 41
R1 R3 = CMP-0097451-1: 10 mOhms ±1% 1W Chip Resistor Wide 0805 (2012 Metric), 0508 Automotive AEC-Q200, Current Sense Metal Foil; Manufacturer: Susumu; SizeZ_mm: 0.7mm; AEC Grade: Grade 0; AEC Qualified: Yes; TempCo: 50ppm/°C
R2 R5 R7 R9-R11 R13-R15 R20 R24 R35 R36 R38 R52 = CMP-0002710-1: 0 Ohms Jumper Chip Resistor 0402 (1005 Metric) Automotive AEC-Q200 Thick Film; Manufacturer: Panasonic; AEC Grade: Grade 0; AEC Qualified: Yes; SizeZ_mm: 0.4mm; Power: 100mW
R4 = CMP-0095678-1: 4 mOhms ±1% 1W Chip Resistor Wide 0805 (2012 Metric), 0508 Automotive AEC-Q200, Current Sense Metal Foil; Manufacturer: Susumu; AEC Grade: Grade 0; TempCo: 50ppm/°C; AEC Qualified: Yes; SizeZ_mm: 0.7mm
R6 R16 R27 R33 R41-R43 R49-R51 R55 = CMP-0023343-3: RES, 0, 1%, 0.1 W, AEC-Q200 Grade 0, 0603; Manufacturer: Stackpole Electronics Inc; Power_W: 100mW; TempCo: ppm/C; U/M: EA; Value: 0; SizeX_mm: 1.6; SizeY_mm: 0.8; SizeZ_mm: 1; Value2: 0.1W; SizeArea_mm2: 1.28; AEC Qualified: Y; AEC Category: Q200
R8 R17 R18 = CMP-0025963-3: RES, 10.0, 1%, 0.063 W, AEC-Q200 Grade 0, 0402; Manufacturer: Vishay-Dale; Power_W: 63mW; TempCo: 100 ppm/C; Value_Code: 10R0; Value: 10.0; EIA_Code: E96; Res_ohm: 10; SizeX_mm: 1; SizeY_mm: 0.5; SizeZ_mm: 0.6; Value2: 0.063W; AEC Qualified: Y; VDC_V: 50V; AEC Category: Q200; AEC Grade: 0
R12 = CMP-0026744-1: RES, 82.0 k, 1%, 0.063 W, 0402; Manufacturer: Yageo America; Power_W: 63mW; TempCo: 100 ppm/C; Value_Code: 82k0; U/M: EA; Value: 82.0k; Res_ohm: 82k; SizeX_mm: 1; SizeY_mm: 0.5; SizeZ_mm: 0.6; Value2: 0.063W; AEC Qualified: N; VDC_V: 50V; AEC Category: Q200
R19 = CMP-0026240-2: RES, 2.67 k, 1%, 0.063 W, AEC-Q200 Grade 0, 0402; Manufacturer: Vishay-Dale; Power_W: 63mW; TempCo: 100 ppm/C; Value_Code: 2k67; Value: 2.67k; EIA_Code: E96; SizeX_mm: 1; SizeY_mm: 0.5; SizeZ_mm: 0.6; Value2: 0.063W; AEC Qualified: Y; VDC_V: 50V; AEC Category: Q200; AEC Grade: 0
R21 = CMP-0026543-2: RES, 75.0 k, 1%, 0.063 W, AEC-Q200 Grade 0, 0402; Manufacturer: Vishay-Dale; Power_W: 63mW; TempCo: 100 ppm/C; Value_Code: 75k0; Value: 75.0k; EIA_Code: E96; Res_ohm: 75k; SizeX_mm: 1; SizeY_mm: 0.5; SizeZ_mm: 0.6; Value2: 0.063W; AEC Qualified: Y; VDC_V: 50V; AEC Category: Q200; AEC Grade: 0
R22 = CMP-0025993-3: RES, 12.7 k, 1%, 0.063 W, AEC-Q200 Grade 0, 0402; Manufacturer: Vishay-Dale; Power_W: 63mW; TempCo: 100 ppm/C; Value_Code: 12k7; Value: 12.7k; EIA_Code: E96; SizeX_mm: 1; SizeY_mm: 0.5; SizeZ_mm: 0.6; Value2: 0.063W; AEC Qualified: Y; VDC_V: 50V; AEC Category: Q200; AEC Grade: 0
R23 R26 = CMP-0018676-3: RES, 3.0, 5%, 0.25 W, AEC-Q200 Grade 0, 1206; Manufacturer: Vishay-Dale; Power_W: 250mW; TempCo: 200 ppm/C; Value_Code: 3R00; Value: 3.0; EIA_Code: E24; Res_ohm: 3; SizeX_mm: 3.2; SizeY_mm: 1.6; SizeZ_mm: 1.35; Value2: 0.25W; SizeArea_mm2: 5.12; AEC Qualified: Y; VDC_V: 200V; AEC Category: Q200; AEC Grade: 0
R25 = CMP-0077124-1: RES, 10.0 k, 0.1%, 0.1 W, AEC-Q200 Grade 0, 0402; Manufacturer: Vishay/Beyschlag; Value_Code: 10k0; SizeArea_mm2: 0.5; AEC Qualified: Y; AEC Category: Q200; Res_ohm: 10k; Value: 10.0k; SizeZ_mm: 0.6; EIA_Code: E192; TempCo: 25 ppm/C; AEC Grade: 0; Power_W: 100mW; VDC_V: 50V; Value2: 0.1W; U/M: EA; SizeX_mm: 1.0
R28 R32 = CMP-0026925-3: RES, 3.0, 5%, 0.063 W, AEC-Q200 Grade 0, 0402; Manufacturer: Vishay-Dale; Power_W: 63mW; TempCo: 200 ppm/C; Value_Code: 3R00; Value: 3.0; EIA_Code: E24; Res_ohm: 3; SizeX_mm: 1; SizeY_mm: 0.5; SizeZ_mm: 0.6; Value2: 0.063W; AEC Qualified: Y; VDC_V: 50V; AEC Category: Q200; AEC Grade: 0
R29 = CMP-0026591-2: RES, 8.66 k, 1%, 0.063 W, AEC-Q200 Grade 0, 0402; Manufacturer: Vishay-Dale; Power_W: 63mW; TempCo: 100 ppm/C; Value_Code: 8k66; Value: 8.66k; EIA_Code: E96; SizeX_mm: 1; SizeY_mm: 0.5; SizeZ_mm: 0.6; Value2: 0.063W; AEC Qualified: Y; VDC_V: 50V; AEC Category: Q200; AEC Grade: 0
R30 = CMP-0026367-2: RES, 40.2 k, 1%, 0.063 W, AEC-Q200 Grade 0, 0402; Manufacturer: Vishay-Dale; Power_W: 63mW; TempCo: 100 ppm/C; Value_Code: 40k2; Value: 40.2k; EIA_Code: E96; SizeX_mm: 1; SizeY_mm: 0.5; SizeZ_mm: 0.6; Value2: 0.063W; AEC Qualified: Y; VDC_V: 50V; AEC Category: Q200; AEC Grade: 0
R31 = CMP-0026028-3: RES, 15.4 k, 1%, 0.063 W, AEC-Q200 Grade 0, 0402; Manufacturer: Vishay-Dale; Power_W: 63mW; TempCo: 100 ppm/C; Value_Code: 15k4; Value: 15.4k; EIA_Code: E96; SizeX_mm: 1; SizeY_mm: 0.5; SizeZ_mm: 0.6; Value2: 0.063W; AEC Qualified: Y; VDC_V: 50V; AEC Category: Q200; AEC Grade: 0
R34 = CMP-0026463-2: RES, 5.11 k, 1%, 0.063 W, AEC-Q200 Grade 0, 0402; Manufacturer: Vishay-Dale; Power_W: 63mW; TempCo: 100 ppm/C; Value_Code: 5k11; Value: 5.11k; EIA_Code: E96; SizeX_mm: 1; SizeY_mm: 0.5; SizeZ_mm: 0.6; Value2: 0.063W; AEC Qualified: Y; VDC_V: 50V; AEC Category: Q200; AEC Grade: 0
R37 = CMP-0026241-2: RES, 2.74 k, 1%, 0.063 W, AEC-Q200 Grade 0, 0402; Manufacturer: Vishay-Dale; Power_W: 63mW; TempCo: 100 ppm/C; Value_Code: 2k74; Value: 2.74k; EIA_Code: E96; SizeX_mm: 1; SizeY_mm: 0.5; SizeZ_mm: 0.6; Value2: 0.063W; AEC Qualified: Y; VDC_V: 50V; AEC Category: Q200; AEC Grade: 0
R39 R40 R44 = CMP-0023000-5: RES, 2.00 k, 1%, 0.1 W, 0603; Manufacturer: Yageo; Power_W: 100mW; TempCo: 100 ppm/C; Value_Code: 2k00; Value: 2.00k; EIA_Code: E96; Res_ohm: 2k; SizeX_mm: 1.6; SizeY_mm: 0.8; SizeZ_mm: 1; Value2: 0.1W; SizeArea_mm2: 1.28; AEC Qualified: N; VDC_V: 75V; AEC Category: Q200; SizeAreaWB_mm2: 4.68
R45 R46 = CMP-0023259-5: RES, 71.5 k, 1%, 0.1 W, 0603; Manufacturer: Yageo; Power_W: 100mW; TempCo: 100 ppm/C; Value_Code: 71k5; Value: 71.5k; EIA_Code: E96; SizeX_mm: 1.6; SizeY_mm: 0.8; SizeZ_mm: 1; Value2: 0.1W; SizeArea_mm2: 1.28; AEC Qualified: N; VDC_V: 75V; AEC Category: Q200; SizeAreaWB_mm2: 4.68
R47 R48 = CMP-0023153-5: RES, 4.70 k, 1%, 0.1 W, 0603; Manufacturer: Yageo; Power_W: 100mW; TempCo: 100 ppm/C; Value_Code: 4k70; Value: 4.70k; Res_ohm: 4.7k; SizeX_mm: 1.6; SizeY_mm: 0.8; SizeZ_mm: 1; Value2: 0.1W; SizeArea_mm2: 1.28; AEC Qualified: N; VDC_V: 75V; AEC Category: Q200; SizeAreaWB_mm2: 4.68
R53 = CMP-0022852-5: RES, 18.0 k, 1%, 0.1 W, 0603; Manufacturer: Yageo; Power_W: 100mW; TempCo: 100 ppm/C; Value_Code: 18k0; Value: 18.0k; Res_ohm: 18k; SizeX_mm: 1.6; SizeY_mm: 0.8; SizeZ_mm: 1; Value2: 0.1W; SizeArea_mm2: 1.28; AEC Qualified: N; VDC_V: 75V; AEC Category: Q200; SizeAreaWB_mm2: 4.68
R54 = CMP-0023653-3: RES, 10.0 k, 0.1%, 0.1 W, 0603; Manufacturer: Yageo America; Power_W: 100mW; TempCo: 25 ppm/C; Value_Code: 10k0; U/M: EA; Value: 10.0k; EIA_Code: E192; Res_ohm: 10k; SizeX_mm: 1.6; SizeY_mm: 0.8; SizeZ_mm: 1; Value2: 0.1W; SizeArea_mm2: 1.28; VDC_V: 75V; AEC Category: Q200
TP1 TP2 TP5 TP6 = CMP-0055140-2: Test Point, Miniature, Orange, TH; Manufacturer: Keystone Electronics; CNHeader: FALSE; Green_Lifecycle: Active; Green_REACh: Passed; ContactFinish: Silver; CT: TRUE
TP3 TP14 = CMP-0055137-2: Test Point, Miniature, Red, TH; Manufacturer: Keystone Electronics; Green_REACh: Passed; Green_Lifecycle: Active; ContactFinish: Silver; CNHeader: FALSE; CT: TRUE
TP4 TP7 TP8 TP15 = CMP-0055138-2: Test Point, Miniature, Black, TH; Manufacturer: Keystone Electronics; CNHeader: FALSE; Green_Lifecycle: Active; Green_REACh: Passed; ContactFinish: Silver; CT: TRUE
TP9-TP13 = CMP-0055141-2: Test Point, Miniature, Yellow, TH; Manufacturer: Keystone Electronics; CNHeader: FALSE; Green_Lifecycle: Active; Green_REACh: Passed; ContactFinish: Silver; CT: TRUE
U1 = CMP-0127273-1: 36V VIN4 Switch Buck-Boost Controller with I2C; Manufacturer: Texas Instruments; SizeZ_mm: 1mm; AEC Qualified: Yes; AEC Grade: Grade 0; Min Supply Voltage: 3.5V; Nominal Supply Current: 65uA; Number Of Outputs: 2; Output Type: AdjustableProgrammable; Standoff Height: 0mm; Switching Frequency: 100-2200kHz; Switching Topology: Boost,Buck,Buck-Boost; TJmax_C: +150°C

## Sheet SR161A_Hardware.SchDoc: LM51772RWE EVM Hardware
size 431 x 279 mm; Date: Not shown in title block; ApprovedBy: Not shown in title block; CheckedBy: Not shown in title block; Author: Not shown in title block; CompanyName: Not shown in title block; Engineer: Not shown in title block; Organization: Not shown in title block; Address1: Not shown in title block; Address2: Not shown in title block; Address3: Not shown in title block; Address4: Not shown in title block; DocumentNumber: 2; Revision: Use project parameter SCH_Rev; SheetNumber: 2; SheetTotal: 2; PageSetup: Record=PageOptions¦CenterHorizontal=True¦CenterVertical=True¦PrintScale=1.00¦XCorrection=1.00¦YCorrection=1.00¦PrintKind=0¦BorderSize=5000000¦LeftOffset=0¦BottomOffset=0¦Orientation=2¦PaperLength=1000¦PaperWidth=1000¦Scale=100¦PaperSource=15¦PrintQuality=600¦MediaType=1¦DitherType=10¦PaperKind=Letter¦PrintScaleMode=1
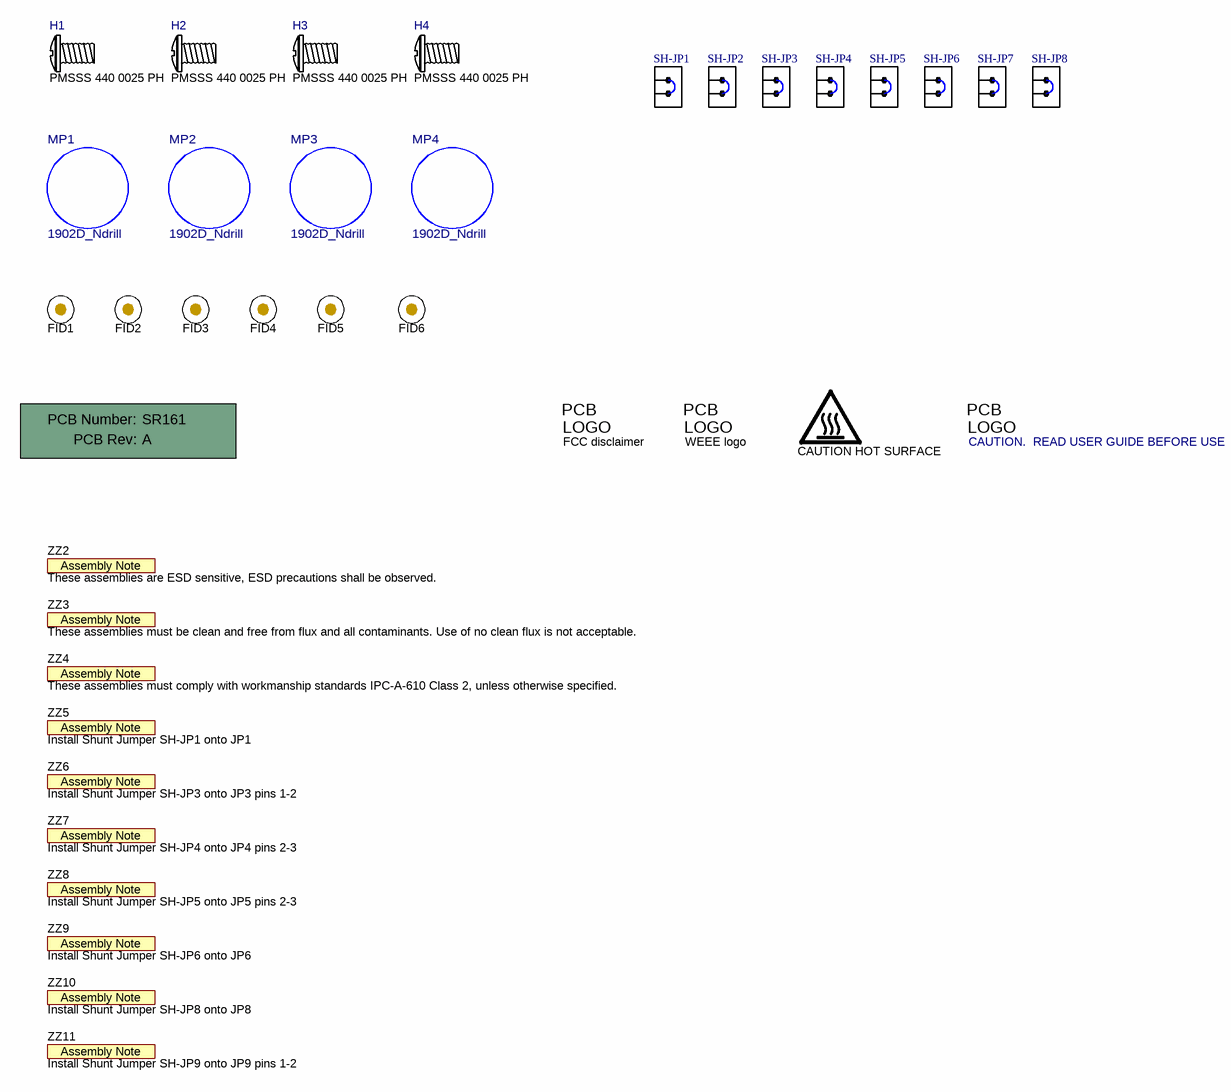
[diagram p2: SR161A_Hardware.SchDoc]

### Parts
!PCB  Printed Circuit Board  (value not drawn)  (mechanical)
FID1  Fiducial  [Fiducial10-20]  (value not drawn)
FID2  Fiducial  [Fiducial10-20]  (value not drawn)
FID3  Fiducial  [Fiducial10-20]  (value not drawn)
FID4  Fiducial  [Fiducial10-20]  (value not drawn)
FID5  Fiducial  [Fiducial10-20]  (value not drawn)
FID6  Fiducial  [Fiducial10-20]  (value not drawn)
H1  PMSSS 440 0025 PH  [B_F_PMSSS4400025PH]
H2  PMSSS 440 0025 PH  [B_F_PMSSS4400025PH]
H3  PMSSS 440 0025 PH  [B_F_PMSSS4400025PH]
H4  PMSSS 440 0025 PH  [B_F_PMSSS4400025PH]
Logo3  FCC disclaimer  [FCC_disclaimer]  (no BOM)
Logo4  WEEE logo  [WEEE_Minimum]  (no BOM)
Logo5  CAUTION HOT SURFACE  [IEC_HotSurface_Small]  (no BOM)
Logo6  CAUTION.  READ USER GUIDE BEFORE USE  [IEC_Caution_Small]  (no BOM)
MP1  1902D_Ndrill  [FP-1902D_Ndrill_HEX_STANDOFF-MFG]
MP2  1902D_Ndrill  [FP-1902D_Ndrill_HEX_STANDOFF-MFG]
MP3  1902D_Ndrill  [FP-1902D_Ndrill_HEX_STANDOFF-MFG]
MP4  1902D_Ndrill  [FP-1902D_Ndrill_HEX_STANDOFF-MFG]
SH-JP1  M7582-05  [Harwin_M7582-05]  (value not drawn)
SH-JP2  M7582-05  [Harwin_M7582-05]  (value not drawn)
SH-JP3  M7582-05  [Harwin_M7582-05]  (value not drawn)
SH-JP4  M7582-05  [Harwin_M7582-05]  (value not drawn)
SH-JP5  M7582-05  [Harwin_M7582-05]  (value not drawn)
SH-JP6  M7582-05  [Harwin_M7582-05]  (value not drawn)
SH-JP7  M7582-05  [Harwin_M7582-05]  (value not drawn)
SH-JP8  M7582-05  [Harwin_M7582-05]  (value not drawn)
ZZ2  These assemblies are ESD sensitive, ESD precautions shall be observed.  [AssemblyNote]  (no BOM)
ZZ3  These assemblies must be clean and free from flux and all contaminants. Use of no clean flux is not acceptable.  [AssemblyNote]  (no BOM)
ZZ4  These assemblies must comply with workmanship standards IPC-A-610 Class 2, unless otherwise specified.  [AssemblyNote]  (no BOM)
ZZ5  Install Shunt Jumper SH-JP1 onto JP1  [AssemblyNote]  (no BOM)
ZZ6  Install Shunt Jumper SH-JP3 onto JP3 pins 1-2  [AssemblyNote]  (no BOM)
ZZ7  Install Shunt Jumper SH-JP4 onto JP4 pins 2-3  [AssemblyNote]  (no BOM)
ZZ8  Install Shunt Jumper SH-JP5 onto JP5 pins 2-3  [AssemblyNote]  (no BOM)
ZZ9  Install Shunt Jumper SH-JP6 onto JP6  [AssemblyNote]  (no BOM)
ZZ10  Install Shunt Jumper SH-JP8 onto JP8  [AssemblyNote]  (no BOM)
ZZ11  Install Shunt Jumper SH-JP9 onto JP9 pins 1-2  [AssemblyNote]  (no BOM)

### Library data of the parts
!PCB = CMP-0003618-2: Manufacturer: Any; PartNumber: SR161
FID1-FID6 = CMP-0077181-1: Fiducial mark.  There is nothing to buy or mount.
H1-H4 = CMP-0003715-1: MACHINE SCREW PAN PHILLIPS 4-40; Manufacturer: B&F Fastener Supply; CompType: Standoff
Logo3 = CMP-0074847-1: FCC_disclaimer; Library Reference: Logo
Logo4 = CMP-0074769-4: Manufacturer: Texas Instruments; CompType: IC; AEC Category: Q200
Logo5 = CMP-0074837-2: IEC 61010-1 Hot Surface Warning; Manufacturer: Texas Instruments; SymbolCreator: a0412235; CompType: IC; AEC Category: Q200
Logo6 = CMP-0074836-1: IEC 61010-1 Caution Warning; SymbolCreator: a0412235; Lib Reference: IEC_Caution
MP1-MP4 = CMP-0090542-1: Hex Standoff Threaded #4-40 Nylon 0.750" (19.05mm) 3/4" Natural; Manufacturer: Keystone Electronics; AEC Qualified: No; SizeZ_mm: 19.43mm
SH-JP1-SH-JP8 = CMP-0078738-1: Single Operation 2.54mm Pitch Open Top Jumper Socket; Manufacturer: Harwin
ZZ2 = CMP-0077236-1
ZZ3 = CMP-0077237-1
ZZ4 = CMP-0077238-1
ZZ5-ZZ11 = CMP-0077238-1: These assemblies must comply with workmanship standards IPC-A-610 Class 2, unless otherwise specified.

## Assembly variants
001: not fitted C7 C17 C18 C19 C22 C35 C38 C40 C44 C45 D3 D4 D5 D6 H1 H2 H3 H4 L2 MP1 MP2 MP3 MP4 R5 R11 R24 R25 R30 R36 R38 R39 R40 R52 SH-JP2 SH-JP4 SH-JP7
